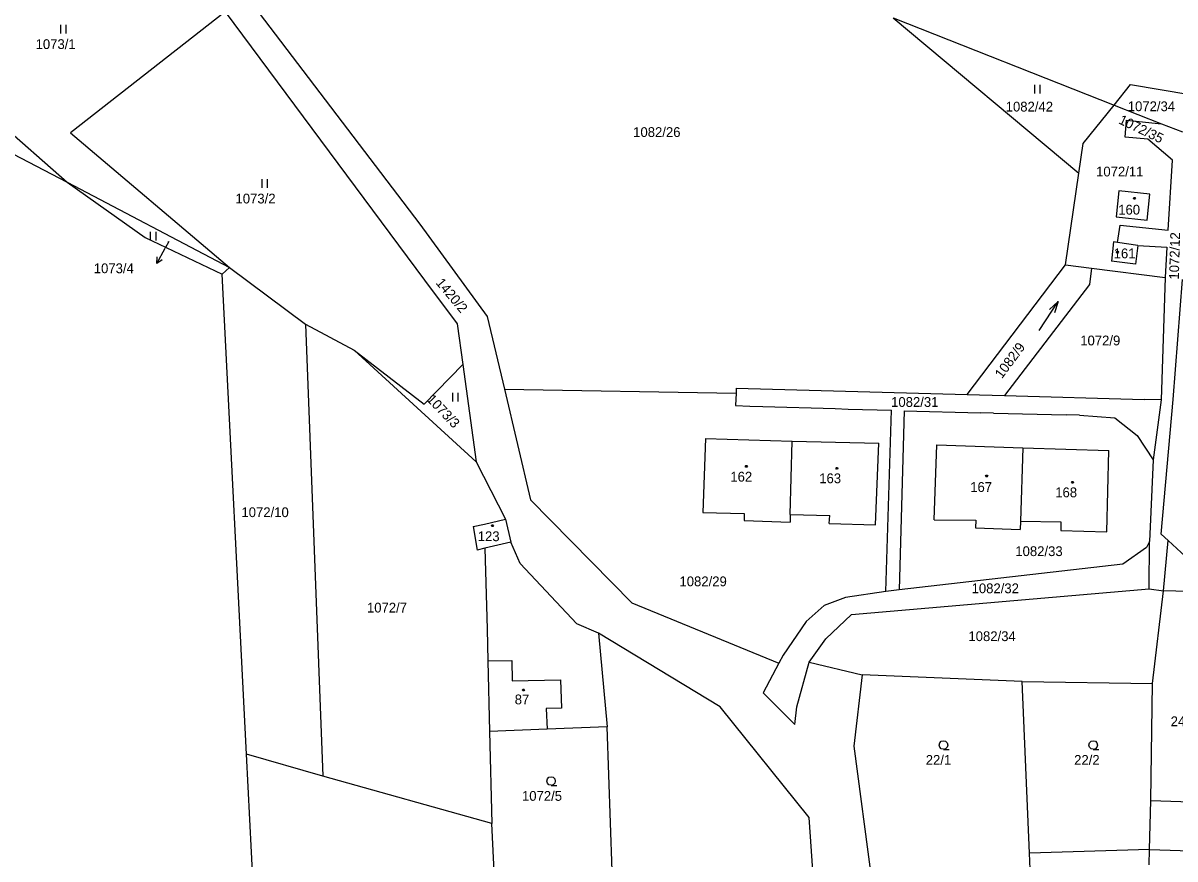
# Model space of a CAD drawing. Extents: x -850689 to -847910, y -1058374 to -1054747.
# Drawn here: x -849716.8 to -849516.8, y -1056299.3 to -1056154.2 of the extents above; entities that cross this region are included whole.
import ezdxf

# ---------------------------------------------------------------- set-up
doc = ezdxf.new("R2010")
doc.units = 0
for name, color, linetype in [('KN_HRANICE', 7, 'Continuous'), ('KN_KULTURY', 7, 'Continuous'), ('KN_PARCELY', 7, 'Continuous'), ('KN_SLUCKY', 7, 'Continuous'), ('KN_STAVEBNI', 7, 'Continuous')]:
    doc.layers.add(name, color=color, linetype=linetype)

# ---------------------------------------------------------------- blocks, each defined once
blk = doc.blocks.new('304')
blk.add_lwpolyline([(0, 0), (-0.38, 0.1), (-0.65, 0.37), (-0.75, 0.74), (-0.65, 1.11), (-0.38, 1.38), (-0.01, 1.48), (0.36, 1.38), (0.63, 1.11), (0.73, 0.73), (0.63, 0.35), (0.36, 0.08), (-0.02, -0.02), (0.98, -0.02)])
blk = doc.blocks.new('306')
for p, q in [((-0.5, 1.5), (-0.5, 0)), ((0.5, 0), (0.5, 1.5))]:
    blk.add_line(p, q)
blk = doc.blocks.new('802')
blk.add_line((-3, 0), (3, 0))
blk.add_lwpolyline([(1, 0.5), (3, 0), (1, -0.5)])
blk = doc.blocks.new('10292')
blk.add_line((0, 3), (0, 0))
blk.add_lwpolyline([(-0.5, 2), (0, 3), (0.5, 2)])
blk = doc.blocks.new('402')
blk.add_lwpolyline([(0.09, 0.15), (0.18, 0), (0.09, -0.15), (-0.09, -0.15), (-0.18, 0), (-0.09, 0.15), (0.09, 0.15)])

msp = doc.modelspace()

# ---------------------------------------------------------------- linework, layer by layer
at = {"layer": 'KN_HRANICE'}
for p, q in [((-849679.02, -1056148.18), (-849647.93, -1056189.13)), ((-849681.71, -1056152.3), (-849708.52, -1056173.28)), ((-849681.71, -1056152.3), (-849647.07, -1056198.84)), ((-849740.13, -1056154.54), (-849709.15, -1056181.86)), ((-849565.73, -1056153.32), (-849533.49, -1056180.31)), ((-849565.73, -1056153.32), (-849527.38, -1056168.45)), ((-849527.38, -1056168.45), (-849524.53, -1056164.91)), ((-849524.53, -1056164.91), (-849514.22, -1056166.62)), ((-849532.73, -1056175.12), (-849527.38, -1056168.45)), ((-849527.38, -1056168.45), (-849519.17, -1056171.69)), ((-849525.47, -1056174.02), (-849525.23, -1056171.06)), ((-849525.23, -1056171.06), (-849519.17, -1056171.69)), ((-849519.17, -1056171.69), (-849515.51, -1056173.13)), ((-849708.52, -1056173.28), (-849680.97, -1056196.64)), ((-849521.53, -1056174.4), (-849525.47, -1056174.02)), ((-849517.22, -1056178.04), (-849521.53, -1056174.4)), ((-849722.68, -1056174.79), (-849709.15, -1056181.86)), ((-849533.49, -1056180.31), (-849532.73, -1056175.12)), ((-849518.02, -1056190.16), (-849517.22, -1056178.04)), ((-849535.83, -1056196.19), (-849533.49, -1056180.31)), ((-849709.15, -1056181.86), (-849680.97, -1056196.64)), ((-849709.15, -1056181.86), (-849695.59, -1056191.46)), ((-849526.56, -1056183.37), (-849527.04, -1056187.89)), ((-849521.2, -1056183.94), (-849526.56, -1056183.37)), ((-849521.67, -1056188.46), (-849521.2, -1056183.94)), ((-849527.04, -1056187.89), (-849521.67, -1056188.46)), ((-849647.93, -1056189.13), (-849636.21, -1056205.16)), ((-849526.8, -1056192.31), (-849526.31, -1056189.3)), ((-849526.31, -1056189.3), (-849518.02, -1056190.16)), ((-849695.59, -1056191.46), (-849682.23, -1056197.8)), ((-849527.49, -1056192.21), (-849527.83, -1056195.55)), ((-849526.8, -1056192.31), (-849527.49, -1056192.21)), ((-849523.27, -1056192.83), (-849526.8, -1056192.31)), ((-849523.27, -1056192.83), (-849523.66, -1056196.06)), ((-849523.27, -1056192.83), (-849518.25, -1056193.14)), ((-849518.25, -1056193.14), (-849518.5, -1056198.37)), ((-849680.97, -1056196.64), (-849682.23, -1056197.8)), ((-849680.97, -1056196.64), (-849667.72, -1056206.47)), ((-849552.87, -1056218.73), (-849535.83, -1056196.19)), ((-849535.83, -1056196.19), (-849531.3, -1056196.76)), ((-849523.66, -1056196.06), (-849527.83, -1056195.55)), ((-849678, -1056281.13), (-849682.23, -1056197.8)), ((-849531.3, -1056196.76), (-849531.68, -1056199.6)), ((-849531.3, -1056196.76), (-849518.5, -1056198.37)), ((-849518.5, -1056198.37), (-849519.23, -1056219.66)), ((-849647.07, -1056198.84), (-849641.41, -1056206.45)), ((-849531.68, -1056199.6), (-849546.39, -1056218.91)), ((-849517.12, -1056219.58), (-849515.49, -1056198.73)), ((-849667.72, -1056206.47), (-849664.73, -1056284.95)), ((-849667.72, -1056206.47), (-849659.31, -1056210.99)), ((-849641.41, -1056206.45), (-849640.45, -1056213.48)), ((-849636.21, -1056205.16), (-849633.22, -1056217.81)), ((-849659.31, -1056210.99), (-849647.14, -1056220.37)), ((-849659.31, -1056210.99), (-849638.15, -1056230.4)), ((-849647.14, -1056220.37), (-849640.45, -1056213.48)), ((-849640.45, -1056213.48), (-849638.15, -1056230.4)), ((-849633.22, -1056217.81), (-849628.68, -1056237)), ((-849633.22, -1056217.81), (-849593, -1056218.48)), ((-849593, -1056218.48), (-849593.09, -1056220.61)), ((-849592.97, -1056217.6), (-849593, -1056218.48)), ((-849592.97, -1056217.6), (-849552.87, -1056218.73)), ((-849593.09, -1056220.61), (-849590.62, -1056220.75)), ((-849552.87, -1056218.73), (-849546.39, -1056218.91)), ((-849546.39, -1056218.91), (-849522.19, -1056219.6)), ((-849519.23, -1056219.66), (-849522.19, -1056219.6)), ((-849519.23, -1056219.66), (-849520.58, -1056230.06)), ((-849519.24, -1056242.93), (-849517.12, -1056219.58)), ((-849590.62, -1056220.75), (-849588.34, -1056220.78)), ((-849588.34, -1056220.78), (-849575.82, -1056221.16)), ((-849575.82, -1056221.16), (-849573.55, -1056221.23)), ((-849573.55, -1056221.23), (-849566.03, -1056221.45)), ((-849567, -1056252.9), (-849566.03, -1056221.45)), ((-849563.83, -1056221.55), (-849564.68, -1056252.6)), ((-849563.83, -1056221.55), (-849550.57, -1056221.9)), ((-849548.32, -1056221.93), (-849550.57, -1056221.9)), ((-849548.32, -1056221.93), (-849535.73, -1056222.24)), ((-849533.4, -1056222.32), (-849535.73, -1056222.24)), ((-849533.4, -1056222.32), (-849527.28, -1056222.76)), ((-849527.28, -1056222.76), (-849523.4, -1056225.85)), ((-849598.32, -1056226.32), (-849598.78, -1056239.21)), ((-849598.32, -1056226.32), (-849583.29, -1056226.79)), ((-849523.4, -1056225.85), (-849520.58, -1056230.06)), ((-849583.59, -1056239.57), (-849583.29, -1056226.79)), ((-849583.29, -1056226.79), (-849568.24, -1056227.17)), ((-849568.82, -1056241.34), (-849568.24, -1056227.17)), ((-849558.62, -1056240.45), (-849558.17, -1056227.46)), ((-849558.17, -1056227.46), (-849543.2, -1056227.96)), ((-849543.2, -1056227.96), (-849543.62, -1056240.68)), ((-849543.2, -1056227.96), (-849528.27, -1056228.45)), ((-849528.65, -1056242.55), (-849528.27, -1056228.45)), ((-849638.15, -1056230.4), (-849633.01, -1056240.36)), ((-849520.58, -1056230.06), (-849521.22, -1056244.23)), ((-849628.68, -1056237), (-849611.09, -1056254.85)), ((-849636.68, -1056241.2), (-849633.01, -1056240.36)), ((-849633.01, -1056240.36), (-849632.08, -1056244.36)), ((-849598.78, -1056239.21), (-849591.59, -1056239.38)), ((-849591.59, -1056239.38), (-849591.62, -1056240.61)), ((-849591.62, -1056240.61), (-849583.62, -1056240.86)), ((-849583.59, -1056239.57), (-849583.62, -1056240.86)), ((-849583.59, -1056239.57), (-849576.72, -1056239.73)), ((-849576.82, -1056241.08), (-849576.72, -1056239.73)), ((-849558.62, -1056240.45), (-849551.38, -1056240.51)), ((-849551.38, -1056240.51), (-849551.46, -1056241.87)), ((-849638.66, -1056241.65), (-849636.68, -1056241.2)), ((-849638.66, -1056241.65), (-849637.96, -1056245.71)), ((-849576.82, -1056241.08), (-849568.82, -1056241.34)), ((-849551.46, -1056241.87), (-849543.67, -1056242.12)), ((-849543.62, -1056240.68), (-849543.67, -1056242.12)), ((-849543.62, -1056240.68), (-849536.61, -1056240.84)), ((-849536.61, -1056240.84), (-849536.64, -1056242.31)), ((-849536.64, -1056242.31), (-849528.65, -1056242.55)), ((-849632.08, -1056244.36), (-849636.59, -1056245.4)), ((-849630.46, -1056248.02), (-849632.08, -1056244.36)), ((-849521.22, -1056244.23), (-849521.78, -1056245.26)), ((-849521.28, -1056252.42), (-849521.22, -1056244.23)), ((-849517.97, -1056244.08), (-849519.24, -1056242.93)), ((-849518.79, -1056252.77), (-849517.97, -1056244.08)), ((-849514.98, -1056246.81), (-849517.97, -1056244.08)), ((-849636.59, -1056245.4), (-849637.96, -1056245.71)), ((-849636.59, -1056245.4), (-849636.24, -1056259.43)), ((-849521.78, -1056245.26), (-849525.87, -1056248.18)), ((-849620.64, -1056258.54), (-849630.46, -1056248.02)), ((-849525.87, -1056248.18), (-849564.68, -1056252.6)), ((-849572.97, -1056256.89), (-849521.28, -1056252.42)), ((-849564.68, -1056252.6), (-849567, -1056252.9)), ((-849521.28, -1056252.42), (-849518.79, -1056252.77)), ((-849574.02, -1056253.95), (-849577.71, -1056255.35)), ((-849567, -1056252.9), (-849574.02, -1056253.95)), ((-849520.73, -1056268.91), (-849518.79, -1056252.77)), ((-849506.8, -1056253.15), (-849518.79, -1056252.77)), ((-849611.09, -1056254.85), (-849585.58, -1056265.38)), ((-849577.71, -1056255.35), (-849580.82, -1056258.14)), ((-849616.86, -1056260.15), (-849620.64, -1056258.54)), ((-849580.82, -1056258.14), (-849584.82, -1056263.95)), ((-849577.42, -1056261.13), (-849572.97, -1056256.89)), ((-849636.24, -1056259.43), (-849636.1, -1056264.92)), ((-849595.77, -1056272.93), (-849616.86, -1056260.15)), ((-849616.86, -1056260.15), (-849615.36, -1056276.4)), ((-849580.29, -1056265.17), (-849577.42, -1056261.13)), ((-849584.82, -1056263.95), (-849585.58, -1056265.38)), ((-849636.1, -1056264.92), (-849635.8, -1056277.2)), ((-849585.58, -1056265.38), (-849588.32, -1056270.53)), ((-849582.46, -1056272.94), (-849580.29, -1056265.17)), ((-849580.29, -1056265.17), (-849571.14, -1056267.35)), ((-849571.14, -1056267.35), (-849572.59, -1056279.79)), ((-849543.36, -1056268.51), (-849571.14, -1056267.35)), ((-849543.36, -1056268.51), (-849520.73, -1056268.91)), ((-849542.09, -1056298.32), (-849543.36, -1056268.51)), ((-849588.32, -1056270.53), (-849582.79, -1056275.99)), ((-849521, -1056289.21), (-849520.73, -1056268.91)), ((-849580.33, -1056292.14), (-849595.77, -1056272.93)), ((-849582.79, -1056275.99), (-849582.46, -1056272.94)), ((-849615.36, -1056276.4), (-849625.82, -1056276.81)), ((-849614.51, -1056301.38), (-849615.36, -1056276.4)), ((-849625.82, -1056276.81), (-849635.8, -1056277.2)), ((-849635.8, -1056277.2), (-849635.4, -1056293.21)), ((-849572.59, -1056279.79), (-849569.5, -1056302.91)), ((-849674.3, -1056351.59), (-849678, -1056281.13)), ((-849664.73, -1056284.95), (-849678, -1056281.13)), ((-849635.4, -1056293.21), (-849664.73, -1056284.95)), ((-849521.24, -1056297.73), (-849521, -1056289.21)), ((-849521, -1056289.21), (-849508.04, -1056289.59)), ((-849578.15, -1056322.42), (-849580.33, -1056292.14)), ((-849634.92, -1056302.69), (-849635.4, -1056293.21)), ((-849521.24, -1056297.73), (-849542.09, -1056298.32)), ((-849541.91, -1056302.5), (-849542.09, -1056298.32)), ((-849521.32, -1056300.37), (-849521.24, -1056297.73))]:
    msp.add_line(p, q, dxfattribs=at)
at = {"layer": 'KN_PARCELY'}
msp.add_line((-849691.47, -1056192.15), (-849692.11, -1056193.32), dxfattribs=at)
at = {"layer": 'KN_SLUCKY'}
for p, q in [((-849636.1, -1056264.92), (-849631.95, -1056264.87)), ((-849631.95, -1056264.87), (-849631.85, -1056268.44)), ((-849631.85, -1056268.44), (-849623.51, -1056268.22)), ((-849623.51, -1056268.22), (-849623.32, -1056273.14)), ((-849623.32, -1056273.14), (-849625.96, -1056273.24)), ((-849625.96, -1056273.24), (-849625.82, -1056276.81)), ((-849521.24, -1056297.73), (-849508.3, -1056298.1))]:
    msp.add_line(p, q, dxfattribs=at)
at = {"layer": 'KN_STAVEBNI'}
for p, q in [((-849526.56, -1056183.37), (-849527.04, -1056187.89)), ((-849521.2, -1056183.94), (-849526.56, -1056183.37)), ((-849521.67, -1056188.46), (-849521.2, -1056183.94)), ((-849527.04, -1056187.89), (-849521.67, -1056188.46)), ((-849527.49, -1056192.21), (-849527.83, -1056195.55)), ((-849526.8, -1056192.31), (-849527.49, -1056192.21)), ((-849523.27, -1056192.83), (-849526.8, -1056192.31)), ((-849523.27, -1056192.83), (-849523.66, -1056196.06)), ((-849523.66, -1056196.06), (-849527.83, -1056195.55)), ((-849598.32, -1056226.32), (-849598.78, -1056239.21)), ((-849598.32, -1056226.32), (-849583.29, -1056226.79)), ((-849583.59, -1056239.57), (-849583.29, -1056226.79)), ((-849583.59, -1056239.57), (-849583.29, -1056226.79)), ((-849583.29, -1056226.79), (-849568.24, -1056227.17)), ((-849568.82, -1056241.34), (-849568.24, -1056227.17)), ((-849558.62, -1056240.45), (-849558.17, -1056227.46)), ((-849558.17, -1056227.46), (-849543.2, -1056227.96)), ((-849543.2, -1056227.96), (-849528.27, -1056228.45)), ((-849528.65, -1056242.55), (-849528.27, -1056228.45)), ((-849636.68, -1056241.2), (-849633.01, -1056240.36)), ((-849633.01, -1056240.36), (-849632.08, -1056244.36)), ((-849598.78, -1056239.21), (-849591.59, -1056239.38)), ((-849591.59, -1056239.38), (-849591.62, -1056240.61)), ((-849591.62, -1056240.61), (-849583.62, -1056240.86)), ((-849583.59, -1056239.57), (-849583.62, -1056240.86)), ((-849583.59, -1056239.57), (-849576.72, -1056239.73)), ((-849576.82, -1056241.08), (-849576.72, -1056239.73)), ((-849558.62, -1056240.45), (-849551.38, -1056240.51)), ((-849551.38, -1056240.51), (-849551.46, -1056241.87)), ((-849638.66, -1056241.65), (-849636.68, -1056241.2)), ((-849638.66, -1056241.65), (-849637.96, -1056245.71)), ((-849576.82, -1056241.08), (-849568.82, -1056241.34)), ((-849551.46, -1056241.87), (-849543.67, -1056242.12)), ((-849543.62, -1056240.68), (-849543.67, -1056242.12)), ((-849543.62, -1056240.68), (-849536.61, -1056240.84)), ((-849536.61, -1056240.84), (-849536.64, -1056242.31)), ((-849536.64, -1056242.31), (-849528.65, -1056242.55)), ((-849632.08, -1056244.36), (-849636.59, -1056245.4)), ((-849636.59, -1056245.4), (-849637.96, -1056245.71)), ((-849636.1, -1056264.92), (-849631.95, -1056264.87)), ((-849636.1, -1056264.92), (-849635.8, -1056277.2)), ((-849631.95, -1056264.87), (-849631.85, -1056268.44)), ((-849631.85, -1056268.44), (-849623.51, -1056268.22)), ((-849623.51, -1056268.22), (-849623.32, -1056273.14)), ((-849623.32, -1056273.14), (-849625.96, -1056273.24)), ((-849625.96, -1056273.24), (-849625.82, -1056276.81)), ((-849625.82, -1056276.81), (-849635.8, -1056277.2)), ((-849521.24, -1056297.73), (-849521, -1056289.21)), ((-849521, -1056289.21), (-849508.04, -1056289.59)), ((-849521.24, -1056297.73), (-849508.3, -1056298.1))]:
    msp.add_line(p, q, dxfattribs=at)

# ---------------------------------------------------------------- block references
at = {"layer": 'KN_KULTURY'}
for name, p in [('306', (-849709.78, -1056156.03)), ('306', (-849540.7, -1056166.46)), ('306', (-849674.84, -1056182.84)), ('402', (-849523.86, -1056184.67)), ('306', (-849694.2, -1056191.98)), ('402', (-849526.8, -1056194)), ('306', (-849641.74, -1056219.93)), ('402', (-849591.23, -1056231.17)), ('402', (-849575.51, -1056231.51)), ('402', (-849549.51, -1056232.88)), ('402', (-849534.6, -1056233.97)), ('402', (-849635.3, -1056241.47)), ('402', (-849629.91, -1056269.99)), ('304', (-849557, -1056280.3)), ('304', (-849531, -1056280.3)), ('304', (-849625.11, -1056286.55))]:
    msp.add_blockref(name, p, dxfattribs=at)
at = {"layer": 'KN_KULTURY', "rotation": 56.60823000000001}
msp.add_blockref('802', (-849538.72, -1056205.07), dxfattribs=at)
at = {"layer": 'KN_PARCELY', "rotation": 151.318154}
msp.add_blockref('10292', (-849692.11, -1056193.32), dxfattribs=at)

# ---------------------------------------------------------------- texts
at = {"layer": 'KN_PARCELY'}
for s, height, p in [('1073/1', 1.7, (-849714.6, -1056158.73)), ('1082/42', 1.7, (-849546.2, -1056169.58)), ('1072/34', 1.7, (-849525.01, -1056169.52)), ('1082/26', 1.7, (-849610.87, -1056174)), ('1072/11', 1.7, (-849530.51, -1056180.85)), ('1073/2', 1.7, (-849679.9, -1056185.54)), ('160', 1.7, (-849526.67, -1056187.47)), ('1073/4', 0.1, (-849691.77, -1056192.15)), ('161', 1.7, (-849527.46, -1056195.06)), ('1073/4', 1.7, (-849704.5, -1056197.65)), ('1072/9', 1.7, (-849533.26, -1056210.18)), ('1082/31', 1.7, (-849566.09, -1056220.86)), ('162', 1.7, (-849594, -1056233.83)), ('163', 1.7, (-849578.57, -1056234.11)), ('167', 1.7, (-849552.36, -1056235.62)), ('168', 1.7, (-849537.6, -1056236.55)), ('1072/10', 1.7, (-849678.87, -1056240)), ('123', 1.7, (-849637.85, -1056244.17)), ('1082/33', 1.7, (-849544.53, -1056246.76)), ('1082/29', 1.7, (-849602.83, -1056252)), ('1082/32', 1.7, (-849552.12, -1056253.21)), ('1072/7', 1.7, (-849657.08, -1056256.56)), ('1082/34', 1.7, (-849552.67, -1056261.52)), ('87', 1.7, (-849631.43, -1056272.5)), ('24/2', 1.7, (-849517.56, -1056276.3)), ('22/1', 1.7, (-849560.08, -1056283)), ('22/2', 1.7, (-849534.32, -1056283)), ('1072/5', 1.7, (-849630.17, -1056289.25))]:
    msp.add_text(s, height=height, dxfattribs=at).set_placement(p)
for s, rotation, p in [('1072/35', 334.378, (-849526.74, -1056171.59)), ('1072/12', 88.407, (-849516.15, -1056198.78)), ('1420/2', 309.97, (-849645.23, -1056199.37)), ('1082/9', 53.342, (-849546.87, -1056216.08)), ('1073/3', 313.58, (-849646.83, -1056219.65))]:
    msp.add_text(s, height=1.7, rotation=rotation, dxfattribs=at).set_placement(p)

doc.saveas('drawing.dxf')
